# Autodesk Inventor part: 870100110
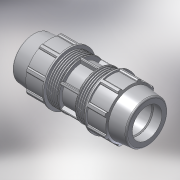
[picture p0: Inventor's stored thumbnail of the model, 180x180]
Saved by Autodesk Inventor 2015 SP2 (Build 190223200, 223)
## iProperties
Created: 2017-02
Part Number: 870100110
Material: PVC-Piping
Description: PLASSON REPAIR COUPLER 110
Document SubType Name: Modeling
Designer: KIM
Mass: 2387.75 g
Surface Area: 2478.17 cm^2
Volume: 1705.54 cm^3
Density: 1.4 g/cm^3
Appearance: Smooth - White
Author: KIM
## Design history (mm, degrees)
derived "87610.ipt"
feature "Solid1::87610.ipt"
tag "TaggingFeature1"
body "Solid1"
other parameters: "d1" = 398, "d4" = 33.16667, "d5" = 56.85714, "d7" = 181, "d8" = 135.75, "d9" = 56.85714, "d11" = 5.68571, "d12" = 144.8, "d13" = 120 deg, "d14" = 143, "d15" = 6 deg, "d16" = 162.9, "d18" = 5.5, "d19" = 35 deg, "d20" = 17.5 deg, "d21" = 168.33, "d23" = 0, "d25" = 360 deg, "d27" = 3.62, "d33" = 2.2, "d34" = 9.05, "d36" = 0, "d37" = 2.2, "d38" = 2.2, "d40" = 360 deg, "d42" = 71.64, "d46" = 3.3, "d50" = 4.975, "d51" = 0, "d53" = 3.63886, "d54" = 3.63886, "d57" = 7.27771, "d62" = 159.642, "E_" = 181, "H_" = 398, "l_" = 143, "d52" = 36.38857
